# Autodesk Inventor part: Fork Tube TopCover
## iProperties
Shininess: 64.0
Length Units: 11272
Angle Units: 11279
Time Units: 11290
Mass Units: 11283
Length Display Precision: 3
Angle Display Precision: 2
Compacted: True
Part Number: Fork Tube TopCover
Document SubType Name: Modeling
Created: 2005-03
Designer: Admin
Manufacturer: Standard
Standards Organization: Custom
Density: 1 g/cm^3
Density: 0.0
Volumn: 0.0
Area: 0.0
PropertySet Name: Model Information
Control State: 0
Master: False
Checked Out: False
Author: Admin
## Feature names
1. ExtrusionBlind1
2. ExtrusionBlind2
3. RevolutionFull1
4. RevolutionFull2
5. Hole1
6. Fillet1
7. Fillet2
